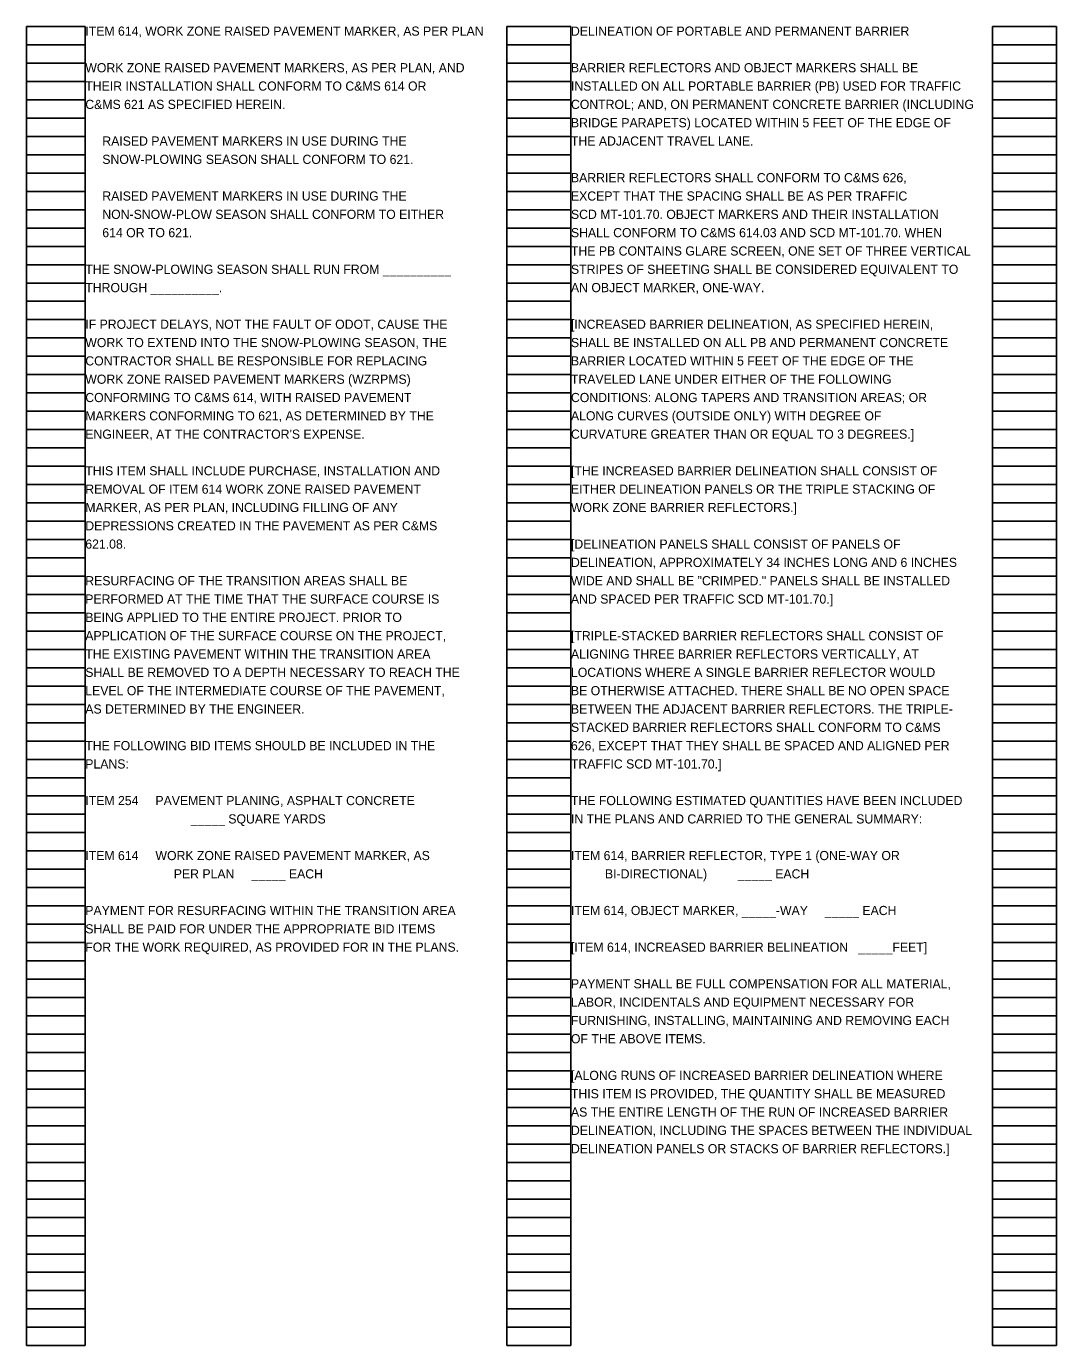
# Model space of a CAD drawing. Extents: x -36 to 68, y -39 to 86.
# Drawn here: x 37.5 to 53.24, y -23.02 to -2.86 of the extents above; entities that cross this region are included whole.
import ezdxf

# ---------------------------------------------------------------- set-up
doc = ezdxf.new("R2010")
doc.units = 0
doc.layers.add('SH_Data', color=7, linetype='Continuous')
doc.layers.add('SH_Text', color=7, linetype='Continuous')

msp = doc.modelspace()

# ---------------------------------------------------------------- linework, layer by layer
at = {"layer": 'SH_Data'}
for p, q in [((37.5, -23.02), (37.5, -2.86)), ((37.5, -2.86), (38.4, -2.86)), ((38.4, -23.02), (38.4, -2.86)), ((44.84, -23.02), (44.84, -2.86)), ((44.84, -2.86), (45.82, -2.86)), ((45.82, -23.02), (45.82, -2.86)), ((52.26, -23.02), (52.26, -2.86)), ((52.26, -2.86), (53.24, -2.86)), ((53.24, -23.02), (53.24, -2.86)), ((37.5, -3.14), (38.4, -3.14)), ((44.84, -3.14), (45.82, -3.14)), ((52.26, -3.14), (53.24, -3.14)), ((37.5, -3.42), (38.4, -3.42)), ((44.84, -3.42), (45.82, -3.42)), ((52.26, -3.42), (53.24, -3.42)), ((37.5, -3.7), (38.4, -3.7)), ((44.84, -3.7), (45.82, -3.7)), ((52.26, -3.7), (53.24, -3.7)), ((37.5, -3.98), (38.4, -3.98)), ((44.84, -3.98), (45.82, -3.98)), ((52.26, -3.98), (53.24, -3.98)), ((37.5, -4.26), (38.4, -4.26)), ((44.84, -4.26), (45.82, -4.26)), ((52.26, -4.26), (53.24, -4.26)), ((37.5, -4.54), (38.4, -4.54)), ((44.84, -4.54), (45.82, -4.54)), ((52.26, -4.54), (53.24, -4.54)), ((37.5, -4.82), (38.4, -4.82)), ((44.84, -4.82), (45.82, -4.82)), ((52.26, -4.82), (53.24, -4.82)), ((37.5, -5.1), (38.4, -5.1)), ((44.84, -5.1), (45.82, -5.1)), ((52.26, -5.1), (53.24, -5.1)), ((37.5, -5.38), (38.4, -5.38)), ((44.84, -5.38), (45.82, -5.38)), ((52.26, -5.38), (53.24, -5.38)), ((37.5, -5.66), (38.4, -5.66)), ((44.84, -5.66), (45.82, -5.66)), ((52.26, -5.66), (53.24, -5.66)), ((37.5, -5.94), (38.4, -5.94)), ((44.84, -5.94), (45.82, -5.94)), ((52.26, -5.94), (53.24, -5.94)), ((37.5, -6.22), (38.4, -6.22)), ((44.84, -6.22), (45.82, -6.22)), ((52.26, -6.22), (53.24, -6.22)), ((37.5, -6.5), (38.4, -6.5)), ((44.84, -6.5), (45.82, -6.5)), ((52.26, -6.5), (53.24, -6.5)), ((37.5, -6.78), (38.4, -6.78)), ((44.84, -6.78), (45.82, -6.78)), ((52.26, -6.78), (53.24, -6.78)), ((37.5, -7.06), (38.4, -7.06)), ((44.84, -7.06), (45.82, -7.06)), ((52.26, -7.06), (53.24, -7.06)), ((37.5, -7.34), (38.4, -7.34)), ((44.84, -7.34), (45.82, -7.34)), ((52.26, -7.34), (53.24, -7.34)), ((37.5, -7.62), (38.4, -7.62)), ((44.84, -7.62), (45.82, -7.62)), ((52.26, -7.62), (53.24, -7.62)), ((37.5, -7.9), (38.4, -7.9)), ((44.84, -7.9), (45.82, -7.9)), ((52.26, -7.9), (53.24, -7.9)), ((37.5, -8.18), (38.4, -8.18)), ((44.84, -8.18), (45.82, -8.18)), ((52.26, -8.18), (53.24, -8.18)), ((37.5, -8.46), (38.4, -8.46)), ((44.84, -8.46), (45.82, -8.46)), ((52.26, -8.46), (53.24, -8.46)), ((37.5, -8.74), (38.4, -8.74)), ((44.84, -8.74), (45.82, -8.74)), ((52.26, -8.74), (53.24, -8.74)), ((37.5, -9.02), (38.4, -9.02)), ((44.84, -9.02), (45.82, -9.02)), ((52.26, -9.02), (53.24, -9.02)), ((37.5, -9.3), (38.4, -9.3)), ((44.84, -9.3), (45.82, -9.3)), ((52.26, -9.3), (53.24, -9.3)), ((37.5, -9.58), (38.4, -9.58)), ((44.84, -9.58), (45.82, -9.58)), ((52.26, -9.58), (53.24, -9.58)), ((37.5, -9.86), (38.4, -9.86)), ((44.84, -9.86), (45.82, -9.86)), ((52.26, -9.86), (53.24, -9.86)), ((37.5, -10.14), (38.4, -10.14)), ((44.84, -10.14), (45.82, -10.14)), ((52.26, -10.14), (53.24, -10.14)), ((37.5, -10.42), (38.4, -10.42)), ((44.84, -10.42), (45.82, -10.42)), ((52.26, -10.42), (53.24, -10.42)), ((37.5, -10.7), (38.4, -10.7)), ((44.84, -10.7), (45.82, -10.7)), ((52.26, -10.7), (53.24, -10.7)), ((37.5, -10.98), (38.4, -10.98)), ((44.84, -10.98), (45.82, -10.98)), ((52.26, -10.98), (53.24, -10.98)), ((37.5, -11.26), (38.4, -11.26)), ((44.84, -11.26), (45.82, -11.26)), ((52.26, -11.26), (53.24, -11.26)), ((37.5, -11.54), (38.4, -11.54)), ((44.84, -11.54), (45.82, -11.54)), ((52.26, -11.54), (53.24, -11.54)), ((37.5, -11.82), (38.4, -11.82)), ((44.84, -11.82), (45.82, -11.82)), ((52.26, -11.82), (53.24, -11.82)), ((37.5, -12.1), (38.4, -12.1)), ((44.84, -12.1), (45.82, -12.1)), ((52.26, -12.1), (53.24, -12.1)), ((37.5, -12.38), (38.4, -12.38)), ((44.84, -12.38), (45.82, -12.38)), ((52.26, -12.38), (53.24, -12.38)), ((37.5, -12.66), (38.4, -12.66)), ((44.84, -12.66), (45.82, -12.66)), ((52.26, -12.66), (53.24, -12.66)), ((37.5, -12.94), (38.4, -12.94)), ((44.84, -12.94), (45.82, -12.94)), ((52.26, -12.94), (53.24, -12.94)), ((37.5, -13.22), (38.4, -13.22)), ((44.84, -13.22), (45.82, -13.22)), ((52.26, -13.22), (53.24, -13.22)), ((37.5, -13.5), (38.4, -13.5)), ((44.84, -13.5), (45.82, -13.5)), ((52.26, -13.5), (53.24, -13.5)), ((37.5, -13.78), (38.4, -13.78)), ((44.84, -13.78), (45.82, -13.78)), ((52.26, -13.78), (53.24, -13.78)), ((37.5, -14.06), (38.4, -14.06)), ((44.84, -14.06), (45.82, -14.06)), ((52.26, -14.06), (53.24, -14.06)), ((37.5, -14.34), (38.4, -14.34)), ((44.84, -14.34), (45.82, -14.34)), ((52.26, -14.34), (53.24, -14.34)), ((37.5, -14.62), (38.4, -14.62)), ((44.84, -14.62), (45.82, -14.62)), ((52.26, -14.62), (53.24, -14.62)), ((37.5, -14.9), (38.4, -14.9)), ((44.84, -14.9), (45.82, -14.9)), ((52.26, -14.9), (53.24, -14.9)), ((37.5, -15.18), (38.4, -15.18)), ((44.84, -15.18), (45.82, -15.18)), ((52.26, -15.18), (53.24, -15.18)), ((37.5, -15.46), (38.4, -15.46)), ((44.84, -15.46), (45.82, -15.46)), ((52.26, -15.46), (53.24, -15.46)), ((37.5, -15.74), (38.4, -15.74)), ((44.84, -15.74), (45.82, -15.74)), ((52.26, -15.74), (53.24, -15.74)), ((37.5, -16.02), (38.4, -16.02)), ((44.84, -16.02), (45.82, -16.02)), ((52.26, -16.02), (53.24, -16.02)), ((37.5, -16.3), (38.4, -16.3)), ((44.84, -16.3), (45.82, -16.3)), ((52.26, -16.3), (53.24, -16.3)), ((37.5, -16.58), (38.4, -16.58)), ((44.84, -16.58), (45.82, -16.58)), ((52.26, -16.58), (53.24, -16.58)), ((37.5, -16.86), (38.4, -16.86)), ((44.84, -16.86), (45.82, -16.86)), ((52.26, -16.86), (53.24, -16.86)), ((37.5, -17.14), (38.4, -17.14)), ((44.84, -17.14), (45.82, -17.14)), ((52.26, -17.14), (53.24, -17.14)), ((37.5, -17.42), (38.4, -17.42)), ((44.84, -17.42), (45.82, -17.42)), ((52.26, -17.42), (53.24, -17.42)), ((37.5, -17.7), (38.4, -17.7)), ((44.84, -17.7), (45.82, -17.7)), ((52.26, -17.7), (53.24, -17.7)), ((37.5, -17.98), (38.4, -17.98)), ((44.84, -17.98), (45.82, -17.98)), ((52.26, -17.98), (53.24, -17.98)), ((37.5, -18.26), (38.4, -18.26)), ((44.84, -18.26), (45.82, -18.26)), ((52.26, -18.26), (53.24, -18.26)), ((37.5, -18.54), (38.4, -18.54)), ((44.84, -18.54), (45.82, -18.54)), ((52.26, -18.54), (53.24, -18.54)), ((37.5, -18.82), (38.4, -18.82)), ((44.84, -18.82), (45.82, -18.82)), ((52.26, -18.82), (53.24, -18.82)), ((37.5, -19.1), (38.4, -19.1)), ((44.84, -19.1), (45.82, -19.1)), ((52.26, -19.1), (53.24, -19.1)), ((37.5, -19.38), (38.4, -19.38)), ((44.84, -19.38), (45.82, -19.38)), ((52.26, -19.38), (53.24, -19.38)), ((37.5, -19.66), (38.4, -19.66)), ((44.84, -19.66), (45.82, -19.66)), ((52.26, -19.66), (53.24, -19.66)), ((37.5, -19.94), (38.4, -19.94)), ((44.84, -19.94), (45.82, -19.94)), ((52.26, -19.94), (53.24, -19.94)), ((37.5, -20.22), (38.4, -20.22)), ((44.84, -20.22), (45.82, -20.22)), ((52.26, -20.22), (53.24, -20.22)), ((37.5, -20.5), (38.4, -20.5)), ((44.84, -20.5), (45.82, -20.5)), ((52.26, -20.5), (53.24, -20.5)), ((37.5, -20.78), (38.4, -20.78)), ((44.84, -20.78), (45.82, -20.78)), ((52.26, -20.78), (53.24, -20.78)), ((37.5, -21.06), (38.4, -21.06)), ((44.84, -21.06), (45.82, -21.06)), ((52.26, -21.06), (53.24, -21.06)), ((37.5, -21.34), (38.4, -21.34)), ((44.84, -21.34), (45.82, -21.34)), ((52.26, -21.34), (53.24, -21.34)), ((37.5, -21.62), (38.4, -21.62)), ((44.84, -21.62), (45.82, -21.62)), ((52.26, -21.62), (53.24, -21.62)), ((37.5, -21.9), (38.4, -21.9)), ((44.84, -21.9), (45.82, -21.9)), ((52.26, -21.9), (53.24, -21.9)), ((37.5, -22.18), (38.4, -22.18)), ((44.84, -22.18), (45.82, -22.18)), ((52.26, -22.18), (53.24, -22.18)), ((37.5, -22.46), (38.4, -22.46)), ((44.84, -22.46), (45.82, -22.46)), ((52.26, -22.46), (53.24, -22.46)), ((37.5, -22.74), (38.4, -22.74)), ((44.84, -22.74), (45.82, -22.74)), ((52.26, -22.74), (53.24, -22.74)), ((37.5, -23.02), (38.4, -23.02)), ((44.84, -23.02), (45.82, -23.02)), ((52.26, -23.02), (53.24, -23.02))]:
    msp.add_line(p, q, dxfattribs=at)

# ---------------------------------------------------------------- texts
at = {"layer": 'SH_Text'}
for s, p in [('ITEM 614, WORK ZONE RAISED PAVEMENT MARKER, AS PER PLAN', (38.4, -3)), ('DELINEATION OF PORTABLE AND PERMANENT BARRIER', (45.82, -3)), ('WORK ZONE RAISED PAVEMENT MARKERS, AS PER PLAN, AND', (38.4, -3.56)), ('BARRIER REFLECTORS AND OBJECT MARKERS SHALL BE', (45.82, -3.56)), ('THEIR INSTALLATION SHALL CONFORM TO C&MS 614 OR', (38.4, -3.84)), ('INSTALLED ON ALL PORTABLE BARRIER (PB) USED FOR TRAFFIC', (45.82, -3.84)), ('C&MS 621 AS SPECIFIED HEREIN.', (38.4, -4.12)), ('CONTROL; AND, ON PERMANENT CONCRETE BARRIER (INCLUDING', (45.82, -4.12)), ('BRIDGE PARAPETS) LOCATED WITHIN 5 FEET OF THE EDGE OF', (45.82, -4.4)), ('     RAISED PAVEMENT MARKERS IN USE DURING THE', (38.4, -4.68)), ('THE ADJACENT TRAVEL LANE.', (45.82, -4.68)), ('     SNOW-PLOWING SEASON SHALL CONFORM TO 621.', (38.4, -4.96)), ('BARRIER REFLECTORS SHALL CONFORM TO C&MS 626,', (45.82, -5.24)), ('     RAISED PAVEMENT MARKERS IN USE DURING THE', (38.4, -5.52)), ('EXCEPT THAT THE SPACING SHALL BE AS PER TRAFFIC', (45.82, -5.52)), ('     NON-SNOW-PLOW SEASON SHALL CONFORM TO EITHER', (38.4, -5.8)), ('SCD MT-101.70. OBJECT MARKERS AND THEIR INSTALLATION', (45.82, -5.8)), ('     614 OR TO 621.', (38.4, -6.08)), ('SHALL CONFORM TO C&MS 614.03 AND SCD MT-101.70. WHEN', (45.82, -6.08)), ('THE PB CONTAINS GLARE SCREEN, ONE SET OF THREE VERTICAL', (45.82, -6.36)), ('THE SNOW-PLOWING SEASON SHALL RUN FROM __________', (38.4, -6.64)), ('STRIPES OF SHEETING SHALL BE CONSIDERED EQUIVALENT TO', (45.82, -6.64)), ('THROUGH __________.', (38.4, -6.92)), ('AN OBJECT MARKER, ONE-WAY.', (45.82, -6.92)), ('IF PROJECT DELAYS, NOT THE FAULT OF ODOT, CAUSE THE', (38.4, -7.48)), ('[INCREASED BARRIER DELINEATION, AS SPECIFIED HEREIN,', (45.82, -7.48)), ('WORK TO EXTEND INTO THE SNOW-PLOWING SEASON, THE', (38.4, -7.76)), ('SHALL BE INSTALLED ON ALL PB AND PERMANENT CONCRETE', (45.82, -7.76)), ('CONTRACTOR SHALL BE RESPONSIBLE FOR REPLACING', (38.4, -8.04)), ('BARRIER LOCATED WITHIN 5 FEET OF THE EDGE OF THE', (45.82, -8.04)), ('WORK ZONE RAISED PAVEMENT MARKERS (WZRPMS)', (38.4, -8.32)), ('TRAVELED LANE UNDER EITHER OF THE FOLLOWING', (45.82, -8.32)), ('CONFORMING TO C&MS 614, WITH RAISED PAVEMENT', (38.4, -8.6)), ('CONDITIONS: ALONG TAPERS AND TRANSITION AREAS; OR', (45.82, -8.6)), ('MARKERS CONFORMING TO 621, AS DETERMINED BY THE', (38.4, -8.88)), ('ALONG CURVES (OUTSIDE ONLY) WITH DEGREE OF', (45.82, -8.88)), ("ENGINEER, AT THE CONTRACTOR'S EXPENSE.", (38.4, -9.16)), ('CURVATURE GREATER THAN OR EQUAL TO 3 DEGREES.]', (45.82, -9.16)), ('THIS ITEM SHALL INCLUDE PURCHASE, INSTALLATION AND', (38.4, -9.72)), ('[THE INCREASED BARRIER DELINEATION SHALL CONSIST OF', (45.82, -9.72)), ('REMOVAL OF ITEM 614 WORK ZONE RAISED PAVEMENT', (38.4, -10)), ('EITHER DELINEATION PANELS OR THE TRIPLE STACKING OF', (45.82, -10)), ('MARKER, AS PER PLAN, INCLUDING FILLING OF ANY', (38.4, -10.28)), ('WORK ZONE BARRIER REFLECTORS.]', (45.82, -10.28)), ('DEPRESSIONS CREATED IN THE PAVEMENT AS PER C&MS', (38.4, -10.56)), ('621.08.', (38.4, -10.84)), ('[DELINEATION PANELS SHALL CONSIST OF PANELS OF', (45.82, -10.84)), ('DELINEATION, APPROXIMATELY 34 INCHES LONG AND 6 INCHES', (45.82, -11.12)), ('RESURFACING OF THE TRANSITION AREAS SHALL BE', (38.4, -11.4)), ('WIDE AND SHALL BE "CRIMPED." PANELS SHALL BE INSTALLED', (45.82, -11.4)), ('PERFORMED AT THE TIME THAT THE SURFACE COURSE IS', (38.4, -11.68)), ('AND SPACED PER TRAFFIC SCD MT-101.70.]', (45.82, -11.68)), ('BEING APPLIED TO THE ENTIRE PROJECT. PRIOR TO', (38.4, -11.96)), ('[TRIPLE-STACKED BARRIER REFLECTORS SHALL CONSIST OF', (45.82, -12.24)), ('APPLICATION OF THE SURFACE COURSE ON THE PROJECT,', (38.4, -12.24)), ('THE EXISTING PAVEMENT WITHIN THE TRANSITION AREA', (38.4, -12.52)), ('ALIGNING THREE BARRIER REFLECTORS VERTICALLY, AT', (45.82, -12.52)), ('SHALL BE REMOVED TO A DEPTH NECESSARY TO REACH THE', (38.4, -12.8)), ('LOCATIONS WHERE A SINGLE BARRIER REFLECTOR WOULD', (45.82, -12.8)), ('LEVEL OF THE INTERMEDIATE COURSE OF THE PAVEMENT,', (38.4, -13.08)), ('BE OTHERWISE ATTACHED. THERE SHALL BE NO OPEN SPACE', (45.82, -13.08)), ('AS DETERMINED BY THE ENGINEER.', (38.4, -13.36)), ('BETWEEN THE ADJACENT BARRIER REFLECTORS. THE TRIPLE-', (45.82, -13.36)), ('STACKED BARRIER REFLECTORS SHALL CONFORM TO C&MS', (45.82, -13.64)), ('THE FOLLOWING BID ITEMS SHOULD BE INCLUDED IN THE', (38.4, -13.92)), ('626, EXCEPT THAT THEY SHALL BE SPACED AND ALIGNED PER', (45.82, -13.92)), ('PLANS:', (38.4, -14.2)), ('TRAFFIC SCD MT-101.70.]', (45.82, -14.2)), ('ITEM 254     PAVEMENT PLANING, ASPHALT CONCRETE', (38.4, -14.76)), ('THE FOLLOWING ESTIMATED QUANTITIES HAVE BEEN INCLUDED', (45.82, -14.76)), ('                               _____ SQUARE YARDS', (38.4, -15.04)), ('IN THE PLANS AND CARRIED TO THE GENERAL SUMMARY:', (45.82, -15.04)), ('ITEM 614     WORK ZONE RAISED PAVEMENT MARKER, AS', (38.4, -15.6)), ('ITEM 614, BARRIER REFLECTOR, TYPE 1 (ONE-WAY OR', (45.82, -15.6)), ('                          PER PLAN     _____ EACH', (38.4, -15.88)), ('          BI-DIRECTIONAL)         _____ EACH', (45.82, -15.88)), ('PAYMENT FOR RESURFACING WITHIN THE TRANSITION AREA', (38.4, -16.44)), ('ITEM 614, OBJECT MARKER, _____-WAY     _____ EACH', (45.82, -16.44)), ('SHALL BE PAID FOR UNDER THE APPROPRIATE BID ITEMS', (38.4, -16.72)), ('FOR THE WORK REQUIRED, AS PROVIDED FOR IN THE PLANS.', (38.4, -17)), ('[ITEM 614, INCREASED BARRIER BELINEATION   _____FEET]', (45.82, -17)), ('PAYMENT SHALL BE FULL COMPENSATION FOR ALL MATERIAL,', (45.82, -17.56)), ('LABOR, INCIDENTALS AND EQUIPMENT NECESSARY FOR', (45.82, -17.84)), ('FURNISHING, INSTALLING, MAINTAINING AND REMOVING EACH', (45.82, -18.12)), ('OF THE ABOVE ITEMS.', (45.82, -18.4)), ('[ALONG RUNS OF INCREASED BARRIER DELINEATION WHERE', (45.82, -18.96)), ('THIS ITEM IS PROVIDED, THE QUANTITY SHALL BE MEASURED', (45.82, -19.24)), ('AS THE ENTIRE LENGTH OF THE RUN OF INCREASED BARRIER', (45.82, -19.52)), ('DELINEATION, INCLUDING THE SPACES BETWEEN THE INDIVIDUAL', (45.82, -19.8)), ('DELINEATION PANELS OR STACKS OF BARRIER REFLECTORS.]', (45.82, -20.08))]:
    msp.add_text(s, height=0.14, dxfattribs=at).set_placement(p)

doc.saveas('drawing.dxf')
